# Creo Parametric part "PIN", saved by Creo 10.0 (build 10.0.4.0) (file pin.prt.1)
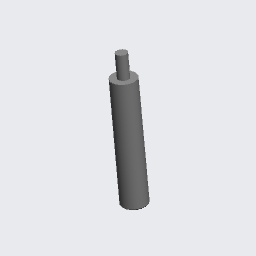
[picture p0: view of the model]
Units: millimeter Kilogram Sec (mmKs); MM, KILOGRAM, SECS

Created from: XX_SOLID_PART_MMKS_NEW_ABS.PRT

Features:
  1. datum plane "RIGHT"
  2. datum plane "TOP"
  3. datum plane "FRONT"
  4. coordinate system
  5. revolve "Revolve 1"
  6. chamfer "Chamfer 1"

Surfaces: 4 cylinder, 3 plane, 2 cone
